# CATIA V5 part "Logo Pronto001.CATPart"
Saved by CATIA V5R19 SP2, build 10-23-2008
Part number: Logo Pronto001
Definition: design
Nomenclature: Logo Pronto001
Source: Unknown
Bounding box of the stored display mesh (mm): x -12.664 to 12.648, y 51.736 to 57.613, z 35 to 36
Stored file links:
  Z:\fausse table rondelle-20220905T211342Z-001\fausse table rondelle\Logo Pronto001.CATPart
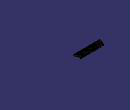
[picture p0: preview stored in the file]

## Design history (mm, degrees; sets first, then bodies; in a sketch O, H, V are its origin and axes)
AxisSystem1: origin (0, 0, 0), X (1, 0, 0), Y (0, 1, 0), Z (0, 0, 1)
Body1 "MANIFOLD_SOLID_BREP #239880" (main body)
  Solid1: solid without history
Body2 "MANIFOLD_SOLID_BREP #240450"
  Solid2: solid without history
Body3 "MANIFOLD_SOLID_BREP #241296"
  Solid3: solid without history
Body4 "MANIFOLD_SOLID_BREP #243043"
  Solid4: solid without history
Body5 "MANIFOLD_SOLID_BREP #243889"
  Solid5: solid without history
Body6 "MANIFOLD_SOLID_BREP #244670"
  Solid6: solid without history
Body7 "MANIFOLD_SOLID_BREP #245240"
  Solid7: solid without history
